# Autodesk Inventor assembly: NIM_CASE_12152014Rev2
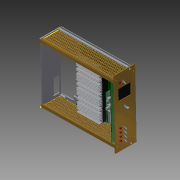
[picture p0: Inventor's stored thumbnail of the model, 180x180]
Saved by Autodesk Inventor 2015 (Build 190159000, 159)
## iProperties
Created: 2014-12
Part Number: NIM_CASE_12152014Rev2
Document SubType Name: Assembly
Designer: idlab
Author: idlab
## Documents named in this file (23)
- C:\Users\idlab\Desktop\PADS-PROJECTS-VIHTORI_VIRTA\HIGH-VOLTAGE-PROJECTS\NG3KV_HV\FINAL FILES\NIM_CASE_12152014Rev2.iam
- C:\Users\idlab\Desktop\PADS-PROJECTS-VIHTORI_VIRTA\HIGH-VOLTAGE-PROJECTS\NG3KV_HV\ALL-IN-ONE\3D\CASE with PCBs and components\BACK_FACE.ipt
- C:\Users\idlab\Desktop\PADS-PROJECTS-VIHTORI_VIRTA\HIGH-VOLTAGE-PROJECTS\NG3KV_HV\ALL-IN-ONE\3D\CASE with PCBs and components\FRONT_FACE.ipt
- C:\Users\idlab\Desktop\PADS-PROJECTS-VIHTORI_VIRTA\HIGH-VOLTAGE-PROJECTS\NG3KV_HV\ALL-IN-ONE\3D\REV_A\Corner Block 1.ipt
- C:\Users\idlab\Desktop\PADS-PROJECTS-VIHTORI_VIRTA\HIGH-VOLTAGE-PROJECTS\NG3KV_HV\ALL-IN-ONE\3D\REV_A\CORNER BLOCK 2.ipt
- C:\Users\idlab\Desktop\PADS-PROJECTS-VIHTORI_VIRTA\HIGH-VOLTAGE-PROJECTS\NG3KV_HV\ALL-IN-ONE\3D\REV_A\Side panel.ipt
- C:\Users\idlab\Desktop\PADS-PROJECTS-VIHTORI_VIRTA\HIGH-VOLTAGE-PROJECTS\NG3KV_HV\ALL-IN-ONE\3D\REV_A\Back and Front Panel.ipt
- C:\Users\idlab\Desktop\PADS-PROJECTS-VIHTORI_VIRTA\HIGH-VOLTAGE-PROJECTS\NG3KV_HV\ALL-IN-ONE\3D\Imported Components\molex\molex.ipt
- C:\Users\idlab\Desktop\PADS-PROJECTS-VIHTORI_VIRTA\HIGH-VOLTAGE-PROJECTS\NG3KV_HV\ALL-IN-ONE\3D\Imported Components\MOLEX_RA\MOLEX_RA.ipt
- C:\Users\idlab\Desktop\PADS-PROJECTS-VIHTORI_VIRTA\Imported Components\Raspberry_B1\Raspberry_B1.ipt
- C:\Users\idlab\Desktop\PADS-PROJECTS-VIHTORI_VIRTA\HIGH-VOLTAGE-PROJECTS\NG3KV_HV\ALL-IN-ONE\3D\Imported Components\ESW-113-33-X-D\ESW-113-33-X-D.ipt
- C:\Users\idlab\Desktop\PADS-PROJECTS-VIHTORI_VIRTA\HIGH-VOLTAGE-PROJECTS\NG3KV_HV\ALL-IN-ONE\3D\Imported Components\RaspberryPi_B\RaspberryPi_B.iam
- C:\Users\idlab\Desktop\PADS-PROJECTS-VIHTORI_VIRTA\HIGH-VOLTAGE-PROJECTS\NG3KV_HV\ALL-IN-ONE\3D\Imported Components\Switch\Switch.ipt
- C:\Users\idlab\Desktop\PADS-PROJECTS-VIHTORI_VIRTA\HIGH-VOLTAGE-PROJECTS\NG3KV_HV\ALL-IN-ONE\3D\Rotary Encoder.ipt
- C:\Users\idlab\Desktop\PADS-PROJECTS-VIHTORI_VIRTA\HIGH-VOLTAGE-PROJECTS\NG3KV_HV\ALL-IN-ONE\3D\DISPLAY.ipt
- C:\Users\idlab\Desktop\PADS-PROJECTS-VIHTORI_VIRTA\HIGH-VOLTAGE-PROJECTS\NG3KV_HV\ALL-IN-ONE\3D\0.1_PITCH-20-PIN-FEMALE-HEADER.ipt
- C:\Users\idlab\Desktop\PADS-PROJECTS-VIHTORI_VIRTA\HIGH-VOLTAGE-PROJECTS\NG3KV_HV\ALL-IN-ONE\3D\Imported Components\TSW-105-05-X-D\TSW-105-05-X-D.ipt
- C:\Users\idlab\Desktop\PADS-PROJECTS-VIHTORI_VIRTA\HIGH-VOLTAGE-PROJECTS\NG3KV_HV\ALL-IN-ONE\3D\Imported Components\DIPLAY_BOARD_12152014\DIPLAY_BOARD_12152014.iam
- C:\Users\idlab\Desktop\PADS-PROJECTS-VIHTORI_VIRTA\HIGH-VOLTAGE-PROJECTS\NG3KV_HV\ALL-IN-ONE\3D\LED.ipt
- C:\Users\idlab\Desktop\PADS-PROJECTS-VIHTORI_VIRTA\HIGH-VOLTAGE-PROJECTS\NG3KV_HV\ALL-IN-ONE\3D\Imported Components\HO_BOARD_12152014REVC\HO_BOARD_12152014REVC.ipt
- C:\Users\idlab\Desktop\PADS-PROJECTS-VIHTORI_VIRTA\HIGH-VOLTAGE-PROJECTS\NG3KV_HV\ALL-IN-ONE\3D\Imported Components\OL-002_AA\OL-002.ipt
- C:\Users\idlab\Desktop\PADS-PROJECTS-VIHTORI_VIRTA\HIGH-VOLTAGE-PROJECTS\NG3KV_HV\ALL-IN-ONE\3D\Imported Components\HS-027\HS-027_REVA_STP-GEN-FILE.ipt
- C:\Users\idlab\Desktop\PADS-PROJECTS-VIHTORI_VIRTA\HIGH-VOLTAGE-PROJECTS\NG3KV_HV\ALL-IN-ONE\3D\Imported Components\MOLEX_3PIN_POWER_CONNECTOR\MOLEX_3PIN_POWER_CONNECTOR.ipt
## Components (47 placed, 22 different names)
1. BACK_FACE:1 — Rigid:8
2. FRONT_FACE:1 — Rigid:1, Rigid:2, Rigid:4, Rigid:5
3. Corner Block 1:1 — Rigid:4, Rigid:6, Rigid:8, Slider:9
4. Corner Block 1:2 — Rigid:1
5. CORNER BLOCK 2:1 — Rigid:5, Rigid:71
6. CORNER BLOCK 2:2 — Rigid:2, Rigid:3, Slider:8
7. Side panel:1 — Rigid:3
8. Side panel:2 — Rigid:6
9. Back and Front Panel:1 — Slider:8
10. MOLEX_RA:1 — Rigid:30, Rigid:67
11. MOLEX_RA:2 — Rigid:27, Rigid:69
12. MOLEX_RA:3 — Rigid:29, Rigid:70
13. MOLEX_RA:4 — Rigid:28, Rigid:68
14. molex:1 — Rigid:27
15. molex:2 — Rigid:28
16. molex:3 — Rigid:29, Rigid:61
17. molex:4 — Rigid:30
18. Raspberry_B1:1
19. ESW-113-33-X-D:1 — Rigid:32, Rigid:55
20. RaspberryPi_B:1 [sub-assembly] — Rigid:32
21. Back and Front Panel:2 — Slider:9
22. Switch:1 — Rigid:53
23. Switch:2 — Rigid:57
24. Switch:3 — Rigid:58
25. Switch:4 — Rigid:59
26. Switch:5 — Rigid:60
27. Rotary Encoder:1 — Rigid:56
28. DISPLAY:1 — Rigid:50
29. 0.1_PITCH-20-PIN-FEMALE-HEADER:1 — Rigid:50, Rigid:51, Rigid:52
30. TSW-105-05-X-D:1 — Rigid:51, Rigid:54
31. TSW-105-05-X-D:2 — Rigid:52
32. DIPLAY_BOARD_12152014:1 [sub-assembly] — Rigid:53, Rigid:54, Rigid:55, Rigid:56, Rigid:57, Rigid:58, Rigid:59, Rigid:60, Rigid:61, Rigid:62, Rigid:66, Rigid:63, Rigid:64, Rigid:65
33. LED:1 — Rigid:62
34. LED:2 — Rigid:66
35. LED:3 — Rigid:63
36. LED:4 — Rigid:64
37. LED:5 — Rigid:65
38. HV_BOARD_12152014REVC:1 — Rigid:67, Rigid:68, Rigid:69, Rigid:70, Rigid:71, Rigid:72, Rigid:73, Rigid:74, Rigid:75, Rigid:80
39. OL-002:1 — Rigid:72, Rigid:77
40. OL-002:2 — Rigid:73, Rigid:76
41. OL-002:3 — Rigid:74, Rigid:78
42. OL-002:4 — Rigid:75, Rigid:79
43. HS-027_REVA_STP-GEN-FILE:1 — Rigid:76
44. HS-027_REVA_STP-GEN-FILE:2 — Rigid:77
45. HS-027_REVA_STP-GEN-FILE:3 — Rigid:79
46. HS-027_REVA_STP-GEN-FILE:4 — Rigid:78
47. MOLEX_3PIN_POWER_CONNECTOR:1 — Rigid:80
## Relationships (45: WeldJoint 43, TranslationJoint 2)
- Rigid:1 [WeldJoint]: FRONT_FACE:1 ↔ Corner Block 1:2
- Rigid:2 [WeldJoint]: FRONT_FACE:1 ↔ CORNER BLOCK 2:2
- Rigid:3 [WeldJoint]: CORNER BLOCK 2:2 ↔ Side panel:1
- Rigid:4 [WeldJoint]: FRONT_FACE:1 ↔ Corner Block 1:1
- Rigid:5 [WeldJoint]: FRONT_FACE:1 ↔ CORNER BLOCK 2:1
- Rigid:6 [WeldJoint]: Corner Block 1:1 ↔ Side panel:2
- Slider:8 [TranslationJoint]: CORNER BLOCK 2:2 ↔ Back and Front Panel:1
- Rigid:8 [WeldJoint]: BACK_FACE:1 ↔ Corner Block 1:1
- Rigid:27 [WeldJoint]: MOLEX_RA:2 ↔ molex:1
- Rigid:28 [WeldJoint]: MOLEX_RA:4 ↔ molex:2
- Rigid:29 [WeldJoint]: MOLEX_RA:3 ↔ molex:3
- Rigid:30 [WeldJoint]: MOLEX_RA:1 ↔ molex:4
- Rigid:32 [WeldJoint]: ESW-113-33-X-D:1 ↔ RaspberryPi_B:1
- Slider:9 [TranslationJoint]: Corner Block 1:1 ↔ Back and Front Panel:2
- Rigid:50 [WeldJoint]: DISPLAY:1 ↔ 0.1_PITCH-20-PIN-FEMALE-HEADER:1
- Rigid:51 [WeldJoint]: 0.1_PITCH-20-PIN-FEMALE-HEADER:1 ↔ TSW-105-05-X-D:1
- Rigid:52 [WeldJoint]: 0.1_PITCH-20-PIN-FEMALE-HEADER:1 ↔ TSW-105-05-X-D:2
- Rigid:53 [WeldJoint]: Switch:1 ↔ DIPLAY_BOARD_12152014:1
- Rigid:54 [WeldJoint]: TSW-105-05-X-D:1 ↔ DIPLAY_BOARD_12152014:1
- Rigid:55 [WeldJoint]: ESW-113-33-X-D:1 ↔ DIPLAY_BOARD_12152014:1
- Rigid:56 [WeldJoint]: Rotary Encoder:1 ↔ DIPLAY_BOARD_12152014:1
- Rigid:57 [WeldJoint]: Switch:2 ↔ DIPLAY_BOARD_12152014:1
- Rigid:58 [WeldJoint]: Switch:3 ↔ DIPLAY_BOARD_12152014:1
- Rigid:59 [WeldJoint]: Switch:4 ↔ DIPLAY_BOARD_12152014:1
- Rigid:60 [WeldJoint]: Switch:5 ↔ DIPLAY_BOARD_12152014:1
- Rigid:61 [WeldJoint]: molex:3 ↔ DIPLAY_BOARD_12152014:1
- Rigid:62 [WeldJoint]: DIPLAY_BOARD_12152014:1 ↔ LED:1
- Rigid:66 [WeldJoint]: DIPLAY_BOARD_12152014:1 ↔ LED:2
- Rigid:63 [WeldJoint]: DIPLAY_BOARD_12152014:1 ↔ LED:3
- Rigid:64 [WeldJoint]: DIPLAY_BOARD_12152014:1 ↔ LED:4
- Rigid:65 [WeldJoint]: DIPLAY_BOARD_12152014:1 ↔ LED:5
- Rigid:67 [WeldJoint]: MOLEX_RA:1 ↔ HV_BOARD_12152014REVC:1
- Rigid:68 [WeldJoint]: MOLEX_RA:4 ↔ HV_BOARD_12152014REVC:1
- Rigid:69 [WeldJoint]: MOLEX_RA:2 ↔ HV_BOARD_12152014REVC:1
- Rigid:70 [WeldJoint]: MOLEX_RA:3 ↔ HV_BOARD_12152014REVC:1
- Rigid:71 [WeldJoint]: CORNER BLOCK 2:1 ↔ HV_BOARD_12152014REVC:1
- Rigid:72 [WeldJoint]: HV_BOARD_12152014REVC:1 ↔ OL-002:1
- Rigid:73 [WeldJoint]: HV_BOARD_12152014REVC:1 ↔ OL-002:2
- Rigid:74 [WeldJoint]: HV_BOARD_12152014REVC:1 ↔ OL-002:3
- Rigid:75 [WeldJoint]: HV_BOARD_12152014REVC:1 ↔ OL-002:4
- Rigid:76 [WeldJoint]: OL-002:2 ↔ HS-027_REVA_STP-GEN-FILE:1
- Rigid:77 [WeldJoint]: OL-002:1 ↔ HS-027_REVA_STP-GEN-FILE:2
- Rigid:78 [WeldJoint]: OL-002:3 ↔ HS-027_REVA_STP-GEN-FILE:4
- Rigid:79 [WeldJoint]: OL-002:4 ↔ HS-027_REVA_STP-GEN-FILE:3
- Rigid:80 [WeldJoint]: HV_BOARD_12152014REVC:1 ↔ MOLEX_3PIN_POWER_CONNECTOR:1
